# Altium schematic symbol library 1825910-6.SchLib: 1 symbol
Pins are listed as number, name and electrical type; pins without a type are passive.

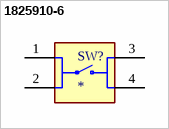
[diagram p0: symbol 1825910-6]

## 1825910-6
designator SW?
FSM4JH=6MM TACT SWITCH, HIGH TEMP; MF: TE Connectivity; MP: 1825910-6
footprint SW_1825910-6-4
pins: 1, 2, 3, 4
